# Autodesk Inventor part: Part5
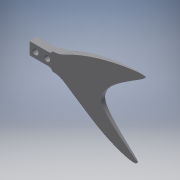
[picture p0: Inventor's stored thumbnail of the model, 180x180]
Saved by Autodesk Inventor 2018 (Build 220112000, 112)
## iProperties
Created: 2019-06
Part Number: Part5
Material: Generic
Document SubType Name: Modeling
Designer: multivac
Density: 1 g/cm^3
Appearance: Default
Author: multivac
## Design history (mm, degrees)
sketch "Sketch1"
  geometry: L1 (-253.727, 92.463)-(88.91, 92.463); L2 (88.91, 92.463)-(88.91, -101.341); L3 (88.91, -101.341)-(-253.727, -101.341); L4 (-253.727, -101.341)-(-253.727, 92.463); L5 (0, -7.62)-(4.104, -7.62); L6 (4.104, -7.62)-(7.826, -10.579); L7 (7.826, -10.579)-(17.653, -17.475); L8 (17.653, -17.475)-(31.143, -27.819); L9 (31.143, -27.819)-(47.563, -34.73); L10 (47.563, -34.73)-(53.475, -34.73); L11 (53.475, -34.73)-(52.526, -32.54); L12 (52.526, -32.54)-(42.453, -24.729); L13 (42.453, -24.729)-(31.065, -13.633); L14 (31.065, -13.633)-(29.386, -8.231); L15 (29.386, -8.231)-(31.868, -2.192); L16 (31.868, -2.192)-(41.358, 6.66); L17 (41.358, 6.66)-(58.512, 16.15); L18 (58.512, 16.15)-(58.512, 17.537); L19 (58.512, 17.537)-(54.497, 18.194); L20 (54.497, 18.194)-(35.153, 15.712); L21 (35.153, 15.712)-(17.268, 10.456); L22 (17.268, 10.456)-(7.413, 5.784); L23 (7.413, 5.784)-(4.493, 3.886); L24 (4.493, 3.886)-(0, 3.886); L25 (0, 3.886)-(0, -7.62); 1 further point; 1 other entity
  constraints: 3 horizontal, 2 end point, 1 perpendicular, 1 vertical, 5 other
extrude "Extrusion1" new body sketch "Sketch1" distance "d36" = 5; taper "d37" = 0 deg
sketch "Sketch2"
  geometry: L1 (0, 0)-(0, 5) reference; L2 (0, 5)-(-61.968, 2.5); L3 (-61.968, 2.5)-(0, 0)
  constraints: 4 end point
extrude "Extrusion2" sketch "Sketch2" distance "d48" = 25; taper "d50" = 0 deg; dims "d49" = 40, "d51" = 0
sketch "Sketch3"
  geometry: L1 (0, 5.753)-(0, 1.753); L2 (0, 1.753)-(5, 1.753); L3 (5, 1.753)-(5, 9.753); L4 (5, 1.753)-(13, 1.753); L5 (5, 9.753)-(0, 9.753); L6 (0, 9.753)-(0, 5.753)
  constraints: 12 end point, 5 perpendicular, 1 horizontal, 1 point on line
  dimensions: "d52" = 4 distance of L1.start L1.end; "d53" = 8 distance of L2.end L3.end; "d54" = 90 deg angle of L4 L3 (derived)
extrude "Extrusion3" join sketch "Sketch3" distance "d55" = 15; taper "d56" = 0 deg
fillet "Fillet1" dims "d57" = 3
sketch "Sketch4"
  geometry: L1 (0, 8)-(0, 0) reference; C1 r 2 at (3.75, 4); C2 r 2 at (11.25, 4)
  constraints: 2 centre point
  dimensions: "d60" = 4 diameter of C1; "d61" = 4 diameter of C2
extrude "Extrusion4" cut sketch "Sketch4" distance "d62" = 15; taper "d63" = 0 deg
body "Solid1"
node "Image1"
